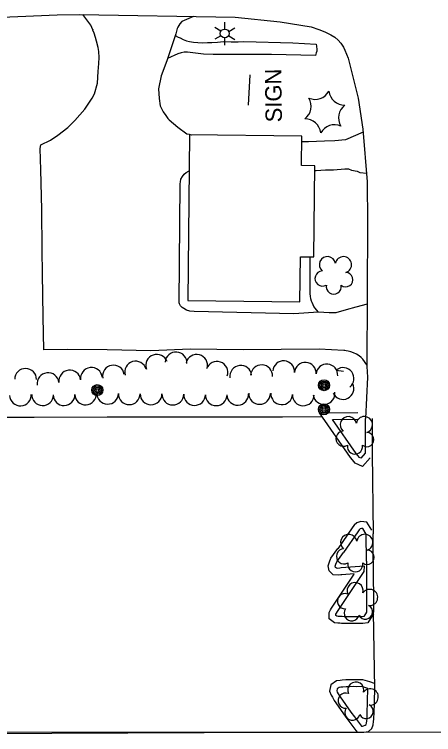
# Model space of a CAD drawing. Extents: x 189384 to 193282, y 256970 to 260388.
# Drawn here: x 190961.3 to 191114.7, y 258010.7 to 258274.2 of the extents above; entities that cross this region are included whole.
import ezdxf

# ---------------------------------------------------------------- set-up
doc = ezdxf.new("R2010")
doc.units = 0
for name, color, linetype in [('E_DWY', 7, 'Continuous'), ('E_LAND_Vegetation', 7, 'Continuous'), ('E_MAP_GridLines', 7, 'Continuous'), ('E_MISCPROP', 7, 'Continuous'), ('E_MISCPROP_HvyLine', 7, 'Continuous'), ('E_PATH_Sidewalk', 7, 'Continuous'), ('E_RDWY', 7, 'Continuous')]:
    doc.layers.add(name, color=color, linetype=linetype)

# ---------------------------------------------------------------- blocks, each defined once
blk = doc.blocks.new('TREE_4')
at = {"layer": 'E_LAND_Vegetation'}
for centre, radius, start, end in [((-1.47, 4.28), 2.78, 1.3945, 209.1675), ((3.57, 2.42), 2.97, 278.4236, 139.6575), ((-4.47, 0.2), 2.78, 78.0715, 279.0825), ((-2.01, -4.2), 2.61, 140.7796, 358.7122), ((3.46, -3.43), 2.97, 196.0744, 79.0477)]:
    blk.add_arc(centre, radius, start, end, dxfattribs=at)
blk = doc.blocks.new('POLE_6')
at = {"layer": 'E_MISCPROP'}
for centre, radius in [((-0.01, 0.02), 2.02), ((-0.01, 0.03), 1.52), ((0, -0.01), 1.01), ((0, 0), 0.502)]:
    blk.add_circle(centre, radius, dxfattribs=at)
blk = doc.blocks.new('SIGN_5')
at = {"layer": 'E_MISCPROP'}
blk.add_text('SIGN', height=6, rotation=0.0001, dxfattribs=at).set_placement((-9.61, -3.01))
blk = doc.blocks.new('LTP_7')
at = {"layer": 'E_MISCPROP'}
for p, q in [((-0.8, 1.43), (-2, 3.73)), ((0.9, 1.42), (2.27, 3.65)), ((-1.64, 0.07), (-4.24, 0.14)), ((-0.88, -1.42), (-2.24, -3.61)), ((0.76, -1.47), (2, -3.65)), ((1.64, -0.02), (4.16, -0.09))]:
    blk.add_line(p, q, dxfattribs=at)
blk.add_circle((0, 0), 1.64, dxfattribs=at)
blk = doc.blocks.new('TREE_6')
at = {"layer": 'E_LAND_Vegetation'}
for centre, radius, start, end in [((-1.47, 4.28), 2.78, 1.3947, 209.1677), ((3.57, 2.42), 2.97, 278.4238, 139.6577), ((-4.47, 0.2), 2.78, 78.0717, 279.0828), ((-2.01, -4.2), 2.61, 140.7799, 358.7125), ((3.46, -3.43), 2.97, 196.0746, 79.0479)]:
    blk.add_arc(centre, radius, start, end, dxfattribs=at)
blk = doc.blocks.new('PINEL_2')
at = {"layer": 'E_LAND_Vegetation'}
for centre, start, end in [((-8.14, 7.32), 275.2115, 0.9764), ((2.26, 10.71), 215.2115, 300.9764), ((10.41, 3.41), 155.2115, 240.9764), ((-10.4, -3.39), 335.2115, 60.9764), ((8.15, -7.3), 95.2115, 180.9764), ((-2.25, -10.7), 35.2115, 120.9764)]:
    blk.add_arc(centre, 5.72, start, end, dxfattribs=at)
blk = doc.blocks.new('TREE_5')
at = {"layer": 'E_LAND_Vegetation'}
for centre, radius, start, end in [((-1.47, 4.28), 2.78, 1.3945, 209.1675), ((3.57, 2.42), 2.97, 278.4236, 139.6575), ((-4.47, 0.2), 2.78, 78.0716, 279.0826), ((-2.01, -4.2), 2.61, 140.7797, 358.7123), ((3.46, -3.43), 2.97, 196.0745, 79.0477)]:
    blk.add_arc(centre, radius, start, end, dxfattribs=at)

msp = doc.modelspace()

# ---------------------------------------------------------------- linework, layer by layer
at = {"layer": 'E_DWY'}
for points in [[(191090.33, 258146.02), (191088.84, 258148.09), (191088.21, 258148.73), (191087.46, 258149.36), (191086.47, 258149.91), (191085.45, 258150.41), (191084.46, 258150.76), (191083.42, 258151.05), (191082.69, 258151.14), (191082.19, 258151.22), (191081.86, 258151.27), (191072.89, 258151.76), (191045.07, 258151.57), (191025.75, 258151.78), (191011.21, 258151.15), (190995.18, 258151.49), (190980.84, 258151.64), (190972.04, 258151.52), (190971.81, 258163.62), (190971.58, 258179.39), (190971.42, 258188.01), (190971.35, 258202.84), (190970.94, 258217.33), (190970.68, 258225.17), (190970.92, 258226.49), (190974.46, 258228.22), (190977.15, 258230.01), (190980.82, 258232.83), (190983.37, 258235.37), (190985.27, 258237.51), (190987.04, 258239.56), (190988.31, 258241.39), (190989.73, 258243.61), (190990.53, 258245.21), (190991.69, 258249.14), (190991.98, 258253.29), (190992.17, 258256.26), (190992.26, 258258.46), (190992.15, 258260.64), (190991.87, 258262.12), (190991.34, 258264.45), (190991, 258265.79), (190990.49, 258267.32), (190990.02, 258268.52), (190989.96, 258268.67), (190989.96, 258268.65), (190989.25, 258270.31), (190986.37, 258274.22)], [(191026.88, 258273.53), (191022.51, 258271.65), (191021.83, 258270.85), (191021.11, 258269.56), (191020.88, 258269.03), (191020.61, 258268.13), (191020.31, 258267.15), (191017.09, 258257.29), (191015.04, 258251.75), (191014.07, 258247.04), (191014.24, 258243.48), (191014.66, 258240.79), (191015.75, 258238.58), (191016.68, 258237.27), (191017.47, 258236.13), (191017.9, 258235.66), (191021.11, 258233.01), (191024.4, 258230.59), (191025.18, 258230.4), (191025.99, 258230.16), (191026.13, 258230.12)], [(191088.89, 258231.21), (191082.46, 258228.34), (191078.63, 258228.03), (191074.76, 258227.81), (191068.96, 258227.58), (191066.54, 258227.63), (191066.5, 258227.63)], [(191090.43, 258168.27), (191086.26, 258167.14), (191082.71, 258166.15), (191078.96, 258165.05), (191076.49, 258165.04), (191072.56, 258165.25), (191063.54, 258164.71), (191027.11, 258165.58), (191025.5, 258165.63), (191024.3, 258165.98), (191023.33, 258166.58), (191022.69, 258167.03), (191022.08, 258167.59), (191021.64, 258168.36), (191021.54, 258168.69), (191021.53, 258168.75), (191021.91, 258212.28), (191022.02, 258212.98), (191022.24, 258214.01), (191022.78, 258214.99), (191023.36, 258215.74), (191024.17, 258216.36), (191025.2, 258216.95)], [(191090.12, 258216.02), (191087.89, 258216.33), (191086.84, 258216.72), (191086.01, 258216.83), (191084.8, 258217.17), (191083.7, 258217.58), (191082.22, 258217.57), (191078.05, 258217.31), (191075.18, 258217.2), (191071.68, 258216.96), (191071.22, 258216.95)], [(191091.55, 258112), (191088.68, 258108.81), (191085.98, 258110.09), (191085.02, 258111.25), (191084.34, 258112.14), (191073, 258128.47), (191086.94, 258128.6)], [(190915.49, 258126.85), (190968.52, 258126.82), (190995.17, 258126.98), (191017.5, 258127.02), (191059.46, 258127.04), (191073.67, 258127.14)], [(191089.69, 258113.67), (191088.07, 258111.87), (191087.56, 258112.11), (191086.98, 258112.81), (191086.36, 258113.61), (191077.75, 258126.01), (191086.97, 258126.1)], [(191092.17, 258085.48), (191090.27, 258088.42), (191088.12, 258088.71), (191086.62, 258088.23), (191085.62, 258087.4), (191085.16, 258086.77), (191084.9, 258086.41), (191079.67, 258078.72)], [(191090.07, 258084.12), (191088.79, 258086.1), (191088.35, 258086.16), (191087.85, 258086), (191087.46, 258085.68), (191087.18, 258085.29), (191086.93, 258084.96), (191081.73, 258077.31)], [(191085.6, 258069.53), (191081.15, 258069.21), (191080.73, 258069.15), (191079.78, 258069.01), (191077.92, 258069.18), (191076.55, 258070.7), (191076.12, 258072.5), (191076.57, 258073.94), (191077.16, 258075.23), (191079.71, 258078.77)], [(191090.21, 258055.52), (191089.16, 258053.95), (191088.53, 258053.83), (191082.02, 258053.88), (191081.21, 258053.94), (191080.44, 258053.99), (191079.83, 258053.99), (191079.32, 258054.04), (191078.96, 258054.31), (191078.97, 258054.78), (191079.2, 258055.21), (191079.5, 258055.73), (191089.28, 258070.37), (191089.4, 258072.31), (191080.87, 258071.7), (191080.35, 258071.62), (191079.71, 258071.52), (191079.12, 258071.58), (191078.84, 258071.9), (191078.71, 258072.42), (191078.91, 258073.05), (191079.33, 258073.97), (191081.73, 258077.31)], [(191092.72, 258054.87), (191092.29, 258054.13), (191090.66, 258051.69), (191088.76, 258051.33), (191081.92, 258051.38), (191081.04, 258051.44), (191080.35, 258051.49), (191079.7, 258051.49), (191078.4, 258051.63), (191076.44, 258053.05), (191076.48, 258055.44), (191077.02, 258056.44), (191077.38, 258057.05), (191085.68, 258069.47)], [(191093.15, 258029.49), (191091.41, 258030.02), (191088.86, 258030.79), (191086.53, 258030.77), (191085.36, 258030.79), (191084.05, 258030.77), (191082.59, 258030.75), (191081.3, 258030.63), (191080.49, 258030.55), (191079.21, 258030.35), (191077.14, 258028.99), (191076.66, 258026.6), (191077.2, 258025.14), (191077.68, 258024.39), (191078.38, 258023.21), (191082.36, 258017.5), (191083.72, 258015.69), (191086.28, 258012.28), (191086.75, 258011.63)], [(191090.69, 258027.63), (191088.5, 258028.29), (191086.52, 258028.27), (191085.36, 258028.29), (191084.09, 258028.27), (191082.73, 258028.26), (191081.55, 258028.14), (191080.8, 258028.07), (191080.13, 258027.96), (191079.38, 258027.47), (191079.25, 258026.8), (191079.45, 258026.27), (191079.81, 258025.7), (191080.48, 258024.56), (191084.38, 258018.97), (191085.72, 258017.19), (191088.28, 258013.78)]]:
    msp.add_lwpolyline(points, dxfattribs=at)
at = {"layer": 'E_LAND_Vegetation'}
msp.add_line((191081.71, 258143.53), (191079.06, 258143.98), dxfattribs=at)
for centre, radius, start, end in [((191013.38, 258145.86), 4, 19.9618, 199.9465), ((191020.43, 258146.73), 4, 356.1773, 176.162), ((191027.96, 258145.8), 4, 345.3432, 165.3279), ((191005.62, 258143.37), 4, 16.0006, 195.9852), ((191035.39, 258143.27), 4, 341.3434, 161.3281), ((191059.82, 258143.5), 3.98, 355.9227, 175.9074), ((191067.77, 258142.94), 3.98, 356.2871, 176.2718), ((190965.36, 258140.7), 3.98, 359.3862, 179.3708), ((190989.47, 258141.04), 4, 6.8868, 186.8715), ((190997.52, 258141.87), 4, 9.6124, 189.5971), ((191044.13, 258141.8), 4, 6.8809, 186.8656), ((191051.75, 258142), 4, 357.095, 177.0797), ((191075.65, 258142.32), 3.98, 354.9174, 174.9021), ((191081.61, 258141.03), 3.98, 307.4111, 127.3958), ((190973.57, 258139.12), 4, 6.8868, 186.8715), ((190981.52, 258140.08), 4, 6.8868, 186.8715), ((191081.56, 258137.37), 3.98, 205.967, 25.9517), ((190963.47, 258135), 3.98, 182.6625, 2.6472), ((190971.57, 258135.1), 3.98, 178.4114, 358.3961), ((190979.44, 258135.1), 3.98, 180.8471, 0.8318), ((190987.31, 258135.38), 3.98, 182.9718, 2.9565), ((190995.41, 258135.64), 3.98, 178.597, 358.5816), ((191003.33, 258135.46), 3.98, 179.7165, 359.7011), ((191011.28, 258135.42), 3.98, 179.7165, 359.7011), ((191019.26, 258135.31), 3.98, 179.0895, 359.0742), ((191027.23, 258135.16), 3.98, 178.8201, 358.8048), ((191035.14, 258135.08), 3.98, 180.0415, 0.0262), ((191042.98, 258135.25), 3.98, 182.9065, 2.8912), ((191051.05, 258135.58), 3.98, 179.5516, 359.5363), ((191059.11, 258135.44), 3.98, 176.777, 356.7617), ((191066.99, 258135.05), 3.98, 178.5555, 358.5402), ((191074.58, 258135.52), 3.98, 187.6266, 7.6113)]:
    msp.add_arc(centre, radius, start, end, dxfattribs=at)
at = {"layer": 'E_MAP_GridLines'}
for p in [(189647.41, 258010.74), (190147.4, 258011.09)]:
    msp.add_line(p, (191647.4, 258012.16), dxfattribs=at)
at = {"layer": 'E_MISCPROP'}
msp.add_line((191046.94, 258241.01), (191047.57, 258252.09), dxfattribs=at)
at = {"layer": 'E_MISCPROP_HvyLine'}
msp.add_lwpolyline([(191025.33, 258230.13), (191024.72, 258169.52), (191065.78, 258169.11), (191065.95, 258185.55), (191070.9, 258185.5), (191071.24, 258218.86), (191066.41, 258218.91), (191066.52, 258229.72)], close=True, dxfattribs=at)
at = {"layer": 'E_PATH_Sidewalk'}
for points in [[(191020.1, 258266.5), (191021.25, 258265.92), (191021.89, 258265.64), (191023, 258265.11), (191024.28, 258264.6), (191025.31, 258264.34), (191026.78, 258264.1), (191028.44, 258263.91), (191030.23, 258263.84), (191031.99, 258263.91), (191033.58, 258263.98), (191035.62, 258264.11), (191037.79, 258264.27), (191040.6, 258264.22), (191043.16, 258264.21), (191045.26, 258264.31), (191063.18, 258263.83), (191071.68, 258263.32), (191071.85, 258262.62), (191072, 258261.41), (191071.96, 258260.79), (191071.79, 258260.19), (191071.66, 258259.7), (191071.48, 258259.15), (191055.43, 258259.53), (191034, 258259.55), (191030.54, 258259.75), (191024.64, 258260.4), (191023.35, 258260.45), (191022.26, 258260.23), (191021.09, 258259.76), (191017.34, 258258.05)], [(191072.59, 258165.25), (191071.85, 258166.12), (191071.38, 258166.74), (191070.92, 258167.42), (191070.58, 258167.99), (191070.25, 258168.79), (191070.06, 258169.28), (191069.77, 258170.14), (191069.67, 258171.11), (191069.59, 258172.05), (191069.55, 258172.69), (191069.52, 258173.06), (191069.59, 258185.51)]]:
    msp.add_lwpolyline(points, dxfattribs=at)
at = {"layer": 'E_RDWY'}
for points in [[(190777.42, 258264.16), (190807.79, 258265.84), (190827.61, 258267.03), (190880.57, 258269.53), (190910.27, 258270.75), (190933.63, 258272.26), (190976.88, 258274.04), (190985.13, 258274.24)], [(190985.13, 258274.24), (191042.11, 258273.27), (191058.51, 258271.53), (191069.85, 258269.74), (191072.66, 258268.7), (191074.91, 258267.87), (191077.09, 258266.82), (191078.52, 258265.96), (191079.74, 258264.78), (191080.72, 258263.73), (191081.8, 258262.27), (191082.22, 258261.15), (191082.81, 258259.64), (191083.42, 258258.2), (191087.09, 258243.65), (191088.8, 258232.31), (191090.36, 258213.01), (191090.55, 258198.15), (191090.33, 258145.43), (191090.47, 258141.5)], [(191090.47, 258141.5), (191089.82, 258126.33)], [(191089.72, 258126.33), (191089.69, 258113.67)], [(191092.22, 258126.33), (191092.19, 258113.66), (191092.57, 258084.14)], [(191090.14, 258074.16), (191090.07, 258084.12)], [(191092.64, 258074.17), (191092.57, 258084.14)], [(191090.14, 258074.16), (191090.21, 258055.52)], [(191092.64, 258074.17), (191092.71, 258055.53)], [(191089.22, 258011.62), (191090.92, 258011.87), (191092.16, 258012.99), (191092.66, 258014.36), (191092.77, 258015.5), (191092.84, 258016.35), (191092.89, 258017.25), (191092.93, 258018.2), (191093.19, 258027.56), (191092.71, 258055.53)], [(191088.28, 258013.78), (191088.68, 258013.88), (191089.11, 258013.97), (191089.69, 258014.13), (191090.02, 258014.43), (191090.2, 258014.91), (191090.28, 258015.73), (191090.35, 258016.52), (191090.39, 258017.36), (191090.43, 258018.28), (191090.69, 258027.63)], [(190816.23, 258011.98), (190875.61, 258011.03), (190946.95, 258011.1), (191030.71, 258011.45), (191078.17, 258011.65), (191089.22, 258011.62)]]:
    msp.add_lwpolyline(points, dxfattribs=at)

# ---------------------------------------------------------------- block references
at = {"layer": 'E_LAND_Vegetation'}
for name, p, xscale, yscale, rotation in [('PINEL_2', (191074.92, 258238.51), 1.000001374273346, 1.0000013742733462, 90.72454528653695), ('TREE_6', (191078.33, 258179.14), 1.0000013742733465, 1.0000013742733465, 90.72454522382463), ('TREE_5', (191086.75, 258059.14), 0.9999977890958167, 0.9999977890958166, 66.02718278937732), ('TREE_5', (191086.99, 258022.76), 0.9999977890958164, 0.9999977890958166, 66.02718278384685)]:
    msp.add_blockref(name, p, dxfattribs=dict(at, xscale=xscale, yscale=yscale, rotation=rotation))
for p, rotation in [((191086.02, 258120.6), 91.26356867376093), ((191086.16, 258077.51), 91.26356866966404)]:
    msp.add_blockref('TREE_4', p, dxfattribs=dict(at, rotation=rotation))
at = {"layer": 'E_MISCPROP', "xscale": 1.0000013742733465}
for name, p, yscale, rotation in [('LTP_7', (191038.28, 258267.26), 1.0000013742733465, 90.72454594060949), ('SIGN_5', (191056.09, 258244.36), 1.0000013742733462, 90.72454562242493)]:
    msp.add_blockref(name, p, dxfattribs=dict(at, yscale=yscale, rotation=rotation))
at = {"layer": 'E_MISCPROP'}
for p, rotation in [((191074.63, 258138.58), 91.26356887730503), ((190991.61, 258136.78), 91.2635703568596), ((191074.6, 258129.77), 91.26356887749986)]:
    msp.add_blockref('POLE_6', p, dxfattribs=dict(at, rotation=rotation))

doc.saveas('drawing.dxf')
